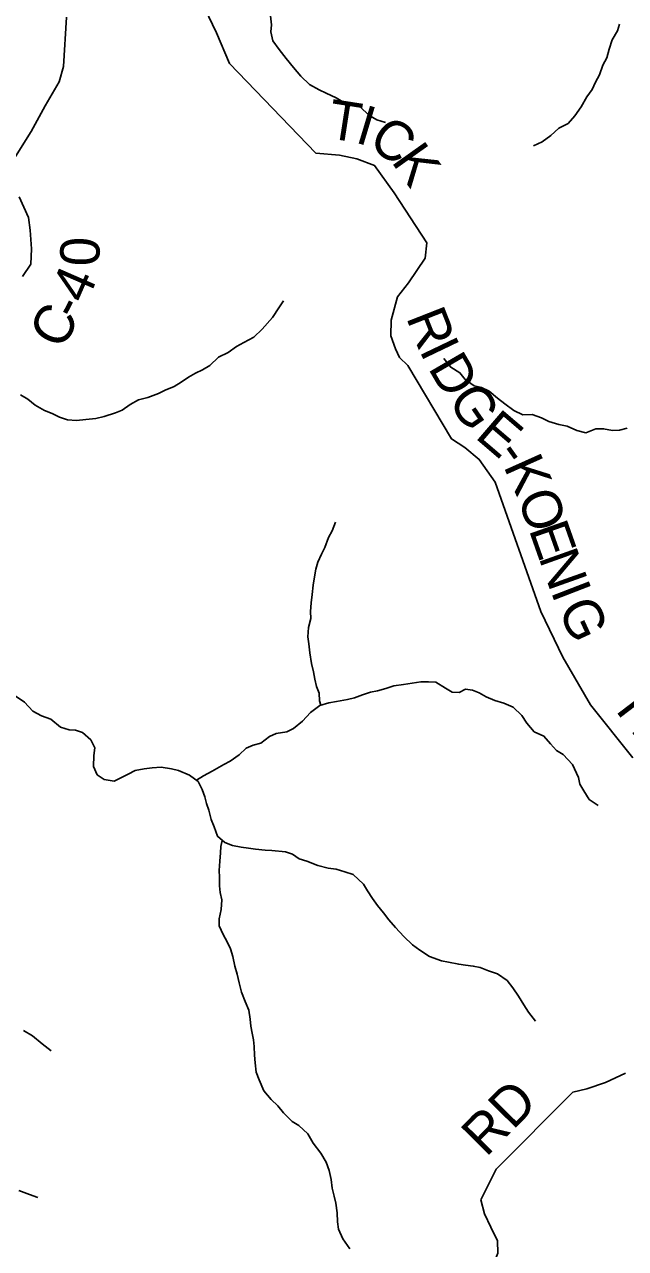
# Model space of a CAD drawing. Extents: x 1624196 to 2029251, y 146837 to 440034.
# Drawn here: x 1758393 to 1762969, y 292767 to 302092 of the extents above; entities that cross this region are included whole.
import ezdxf

# ---------------------------------------------------------------- set-up
doc = ezdxf.new("R2010")
doc.units = 0
for name, color, linetype in [('GM_X_County_Road', 7, 'Continuous'), ('GM_X_County_Road_Text', 7, 'Continuous'), ('GM_X_Minor_River', 7, 'Continuous'), ('GM_X_Township_Road', 7, 'Continuous'), ('GM_X_Township_Road_Text', 7, 'Continuous')]:
    doc.layers.add(name, color=color, linetype=linetype)

msp = doc.modelspace()

# ---------------------------------------------------------------- linework, layer by layer
at = {"layer": 'GM_X_County_Road'}
for points in [[(1759650.1, 302459.9), (1759855, 302028.4), (1759954.5, 301795.6), (1760610.8, 301112.4), (1760790.7, 301095.9), (1760924.7, 301069.5), (1761058.5, 301017), (1761208, 300810.2), (1761457, 300428.7), (1761442.8, 300312.4), (1761316.3, 300124.3), (1761234, 300016.3), (1761185.6, 299838), (1761181.3, 299719.7), (1761219, 299621.3), (1761248.9, 299555.1), (1761310.7, 299494.8), (1761645.3, 298934.7), (1761745.1, 298870.3), (1761854.9, 298777.8), (1761976.5, 298605.2), (1762324, 297620), (1762491.1, 297270.8), (1762702.2, 296907.5), (1763025.1, 296503.8)], [(1758286.1, 301024.4), (1758444.7, 301275.3), (1758550.7, 301472.6), (1758658.5, 301653.9), (1758689.8, 301771.9), (1758713.6, 302146.4)], [(1758379.3, 300171.7), (1758442.3, 300265.3), (1758447.4, 300381.5), (1758436.9, 300525.8), (1758423.9, 300622.2), (1758351.6, 300779.2)]]:
    msp.add_lwpolyline(points, dxfattribs=at)
at = {"layer": 'GM_X_Minor_River'}
for points in [[(1760267.1, 302156.8), (1760272.6, 302088.6), (1760268.3, 302036.5), (1760283.8, 301968.2), (1760333.4, 301901.7), (1760385, 301833.2), (1760440.6, 301764.7), (1760498.2, 301698.1), (1760563.8, 301633.5), (1760637.7, 301594.9), (1760689.6, 301568.5), (1760765.4, 301534), (1760817.2, 301501.5), (1760887.2, 301479), (1760949.1, 301464.6), (1761014.8, 301400), (1761076.6, 301365.5), (1761142.5, 301345)], [(1762923.5, 302093.7), (1762907.1, 302043.7), (1762866.6, 301975.7), (1762844.1, 301903.7), (1762827.7, 301837.6), (1762797.2, 301781.6), (1762770.7, 301707.6), (1762740.3, 301651.7), (1762713.9, 301595.7), (1762673.5, 301539.8), (1762630.9, 301463.9), (1762584.4, 301396), (1762532, 301338.1), (1762461.7, 301302.5), (1762401.2, 301246.7), (1762334.8, 301199), (1762268.5, 301167.4)], [(1758363.5, 299271.2), (1758419.3, 299236.8), (1758475.1, 299192.3), (1758544.9, 299151.8), (1758604.8, 299127.3), (1758660.6, 299100.9), (1758720.6, 299080.5), (1758788.6, 299074), (1758860.7, 299081.6), (1758936.9, 299091.1), (1758999, 299104.8), (1759085.3, 299132.3), (1759137.5, 299154), (1759197.9, 299195.7), (1759260.2, 299231.4), (1759332.4, 299249), (1759412.7, 299280.6), (1759464.9, 299306.3), (1759533.2, 299333.9), (1759585.4, 299365.7), (1759641.8, 299405.4), (1759694, 299435.2), (1759748.3, 299460.9), (1759804.5, 299492.6), (1759871, 299556.4), (1759943.4, 299594), (1760007.8, 299639.7), (1760064, 299669.4), (1760138.4, 299709.1), (1760202.9, 299770.8), (1760281.5, 299858.5), (1760330.1, 299934.4), (1760364.5, 299986.3)], [(1762982.7, 299017.1), (1762922.5, 299001.4), (1762870.5, 298999.7), (1762802.5, 299012.2), (1762742.4, 299010.6), (1762666.1, 298981), (1762598.2, 298997.5), (1762524.3, 299032), (1762460.3, 299044.5), (1762384.4, 299067), (1762330.6, 299095.4), (1762258.6, 299120), (1762186.6, 299118.4), (1762118.7, 299150.9), (1762049, 299201.5), (1761993.2, 299246), (1761931.5, 299298.5), (1761873.6, 299325), (1761817.7, 299339.4), (1761747.9, 299387.9), (1761708.2, 299438.3), (1761638.4, 299480.9), (1761586.8, 299547.4)], [(1760648.2, 296906.3), (1760640, 296938.6), (1760636.5, 296998.8), (1760616.8, 297049), (1760603.1, 297103.3), (1760593.5, 297159.5), (1760577.9, 297223.7), (1760566.5, 297304), (1760556.9, 297372.3), (1760551.3, 297426.4), (1760555.8, 297496.6), (1760572.2, 297566.7), (1760570.6, 297618.8), (1760577.1, 297687), (1760583.5, 297749.1), (1760592, 297819.2), (1760602.4, 297883.3), (1760610.9, 297941.4), (1760627.2, 297995.4), (1760653.7, 298055.4), (1760680.1, 298107.4), (1760708.6, 298183.4), (1760735, 298235.4), (1760761.5, 298301.4)], [(1759703, 296333.7), (1759757.2, 296366.8), (1759821.5, 296402.5), (1759909.9, 296454), (1759960.2, 296479.8), (1760028.6, 296527.5), (1760081, 296579.2), (1760133.2, 296601), (1760193.4, 296616.6), (1760259.8, 296666.3), (1760310, 296690.1), (1760390.2, 296703.6), (1760442.4, 296729.3), (1760510.8, 296783), (1760571.4, 296850.8), (1760641.8, 296904.5), (1760710, 296924.1), (1760768.1, 296933.8), (1760852.3, 296949.3), (1760906.5, 296963), (1760966.7, 296984.6), (1761026.9, 297004.3), (1761081, 297016), (1761143.2, 297033.6), (1761205.4, 297053.3), (1761279.6, 297064.8), (1761343.7, 297072.5), (1761411.9, 297084), (1761469.9, 297083.7), (1761524, 297081.3), (1761597.7, 297036.7), (1761649.6, 297006.3), (1761701.6, 297002), (1761751.9, 297027.7), (1761803.9, 297021.4), (1761855.8, 297001), (1761907.6, 296970.6), (1761973.5, 296942.1), (1762041.4, 296921.6), (1762113.3, 296891.1), (1762179, 296828.5), (1762216.6, 296770.1), (1762274.2, 296703.5), (1762348.1, 296671), (1762397.7, 296610.5), (1762443.4, 296560.1), (1762495.3, 296529.7), (1762564.8, 296455), (1762612.2, 296354.5), (1762621.9, 296304.3), (1762651.6, 296254), (1762691.1, 296187.5), (1762760.9, 296141)], [(1758315.8, 296981.6), (1758393.5, 296929), (1758457.1, 296860.4), (1758523, 296825.8), (1758592.9, 296799.3), (1758668.5, 296738.7), (1758732.5, 296718.2), (1758782.5, 296715.9), (1758834.4, 296697.5), (1758898.1, 296643), (1758927.7, 296580.6), (1758921.3, 296522.5), (1758918.8, 296438.3), (1758946.4, 296376), (1759000.2, 296339.5), (1759076.2, 296327), (1759126.4, 296352.8), (1759182.7, 296380.5), (1759236.9, 296408.2), (1759305.1, 296421.8), (1759365.2, 296429.4), (1759433.3, 296433), (1759513.3, 296420.5), (1759565.2, 296408.1), (1759649.1, 296373.5), (1759714.8, 296324.9), (1759746.5, 296264.6), (1759766.1, 296208.3), (1759779.8, 296158.1), (1759797.4, 296105.8), (1759815, 296035.5), (1759836.6, 295979.3), (1759862.2, 295906.9), (1759917.9, 295860.4), (1759975.8, 295838), (1760041.8, 295825.5), (1760099.8, 295817.2), (1760151.8, 295808.8), (1760225.8, 295802.3), (1760275.9, 295798), (1760379.9, 295789.3), (1760433.8, 295770.9), (1760485.7, 295736.5), (1760541.6, 295718.1), (1760625.5, 295685.5), (1760705.4, 295664.9), (1760765.4, 295656.5), (1760833.4, 295636), (1760895.3, 295615.5), (1760974.9, 295542.8), (1761004.6, 295492.5), (1761042.2, 295434.1), (1761079.9, 295379.7), (1761125.6, 295325.3), (1761167.2, 295270.9), (1761216.9, 295212.4), (1761282.5, 295143.8), (1761348.2, 295081.2), (1761403.9, 295040.8), (1761477.7, 294990.2), (1761567.5, 294957.5), (1761621.5, 294947.1), (1761699.5, 294932.6), (1761751.5, 294924.2), (1761809.5, 294917.9), (1761861.5, 294907.5), (1761925.4, 294881), (1761995.3, 294858.5), (1762069.1, 294807.9), (1762110.7, 294751.5), (1762154.4, 294689), (1762196, 294622.6), (1762229.6, 294568.2), (1762283.2, 294497.7)], [(1759899, 295876.2), (1759887.7, 295830.5), (1759885.3, 295780.4), (1759880.9, 295718.3), (1759876.4, 295646.1), (1759878.1, 295596), (1759877.6, 295529.8), (1759883.3, 295479.7), (1759896.9, 295423.4), (1759890.4, 295349.3), (1759875.9, 295277.2), (1759875.5, 295225), (1759907.1, 295158.7), (1759936.8, 295104.3), (1759962.4, 295050), (1759980, 294991.8), (1759995.6, 294917.5), (1760013.2, 294857.2), (1760028.7, 294790.9), (1760044.3, 294720.6), (1760073.8, 294648.3), (1760101.4, 294581.9), (1760110.9, 294513.7), (1760116.6, 294461.5), (1760126.2, 294407.3), (1760135.9, 294357.1), (1760141.6, 294306.9), (1760145.1, 294238.7), (1760148.7, 294180.6), (1760158.3, 294110.3), (1760179.9, 294052), (1760215.3, 293967.6), (1760271, 293903), (1760322.7, 293852.6), (1760364.4, 293800.2), (1760430, 293735.6), (1760481.9, 293705.2), (1760549.5, 293640.6), (1760591.1, 293570.1), (1760650.6, 293493.5), (1760690.2, 293425.1), (1760711.8, 293360.8), (1760727.3, 293292.5), (1760734.9, 293226.3), (1760750.5, 293166), (1760764.1, 293111.8), (1760773.7, 293039.5), (1760775.2, 292969.3), (1760784.8, 292913.1), (1760816.4, 292840.7), (1760869.9, 292764.2)], [(1758386.5, 294428.5), (1758454.3, 294386), (1758527.9, 294325.3), (1758597.6, 294272.8)], [(1758350.2, 293209.5), (1758432.1, 293178.9), (1758496, 293154.4)]]:
    msp.add_lwpolyline(points, dxfattribs=at)
at = {"layer": 'GM_X_Township_Road'}
msp.add_lwpolyline([(1761226.3, 291692.7), (1761226.6, 291693.3), (1761285.3, 291799.1), (1761423.9, 292019.3), (1761564.2, 292155.3), (1761660.6, 292331.4), (1761843.1, 292503.4), (1761943.3, 292597.4), (1761997.7, 292731.6), (1761993.9, 292825.8), (1761944.1, 292930.2), (1761894.4, 293030.5), (1761866.7, 293138.8), (1761985.2, 293371.1), (1762568.7, 293957.1), (1762674.8, 293982.8), (1762816.9, 294032.6), (1762969.1, 294102.4)], dxfattribs=at)

# ---------------------------------------------------------------- texts
at = {"layer": 'GM_X_County_Road_Text'}
for s, rotation, p in [('T', 351.18802, (1760691.2, 301227.5)), ('I', 343.2858, (1760902.2, 301195.6)), ('C', 325.15699, (1760997.7, 301171)), ('K', 305.40387, (1761180.6, 301049.4)), ('0', 88.83488, (1758963.1, 300247.4)), ('4', 66.44093, (1758862, 299953.8)), ('-', 63.03328, (1758797.8, 299826.3)), ('C', 62.31953, (1758681.5, 299604.5)), ('R', 291.43542, (1761296.5, 299861.6)), ('I', 295.62419, (1761396.1, 299610.3)), ('D', 300.2073, (1761461.7, 299476.1)), ('G', 304.77042, (1761608.5, 299225.9)), ('E', 319.42874, (1761815.1, 298947.1)), ('-', 305.58487, (1761972.7, 298815.2)), ('K', 294.13042, (1762036.5, 298728.7)), ('O', 289.56047, (1762142, 298493.7)), ('E', 289.42839, (1762230.4, 298245.1)), ('N', 289.62396, (1762305.4, 298032.4)), ('I', 291.16232, (1762397.1, 297775.5)), ('G', 294.78546, (1762449.7, 297641.6)), ('HILL', 307.29395, (1762888, 296867.6))]:
    msp.add_text(s, height=300, rotation=rotation, dxfattribs=at).set_placement(p)
at = {"layer": 'GM_X_Township_Road_Text'}
msp.add_text('RD', height=300, rotation=45.34838, dxfattribs=at).set_placement((1761907.1, 293457.7))

doc.saveas('drawing.dxf')
